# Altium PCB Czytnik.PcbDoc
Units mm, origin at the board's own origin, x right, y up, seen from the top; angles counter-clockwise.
Board outline 102 x 67 mm, 2 copper layers (Top Layer, Bottom Layer); 21 components, 15 nets, 82 pads, 16 vias.
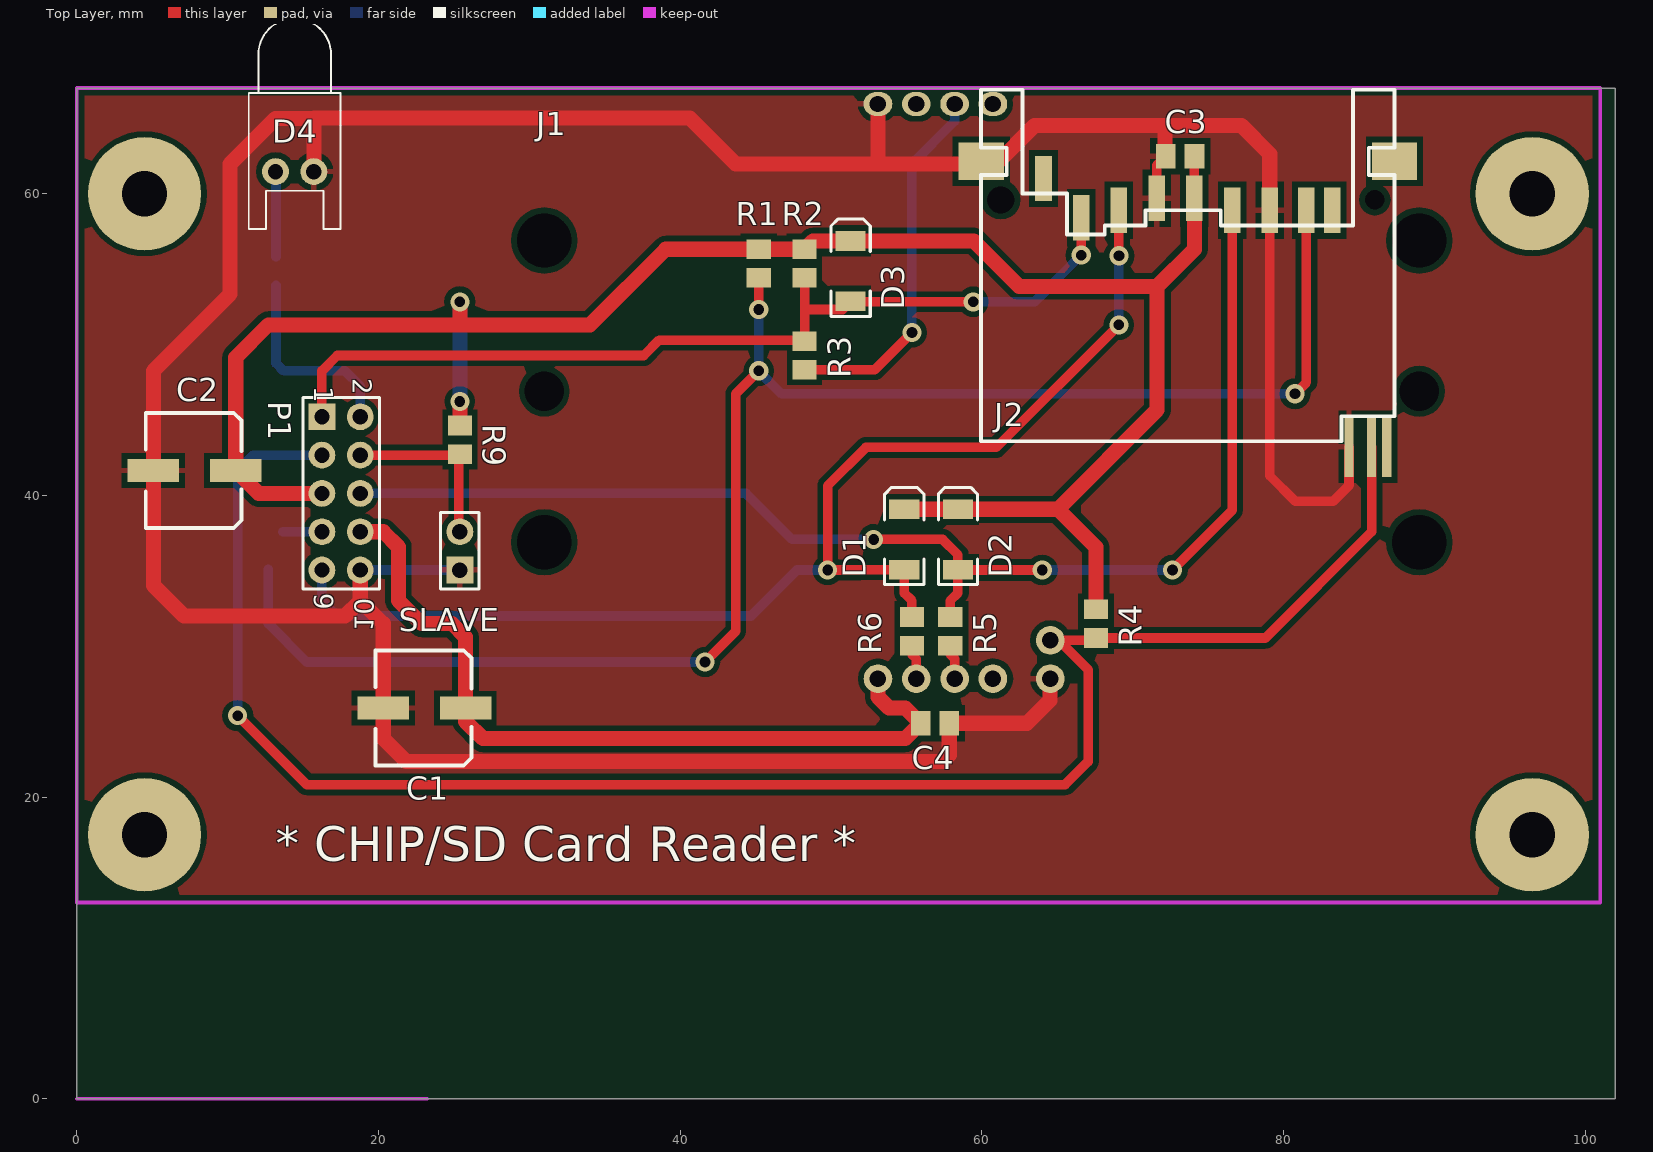
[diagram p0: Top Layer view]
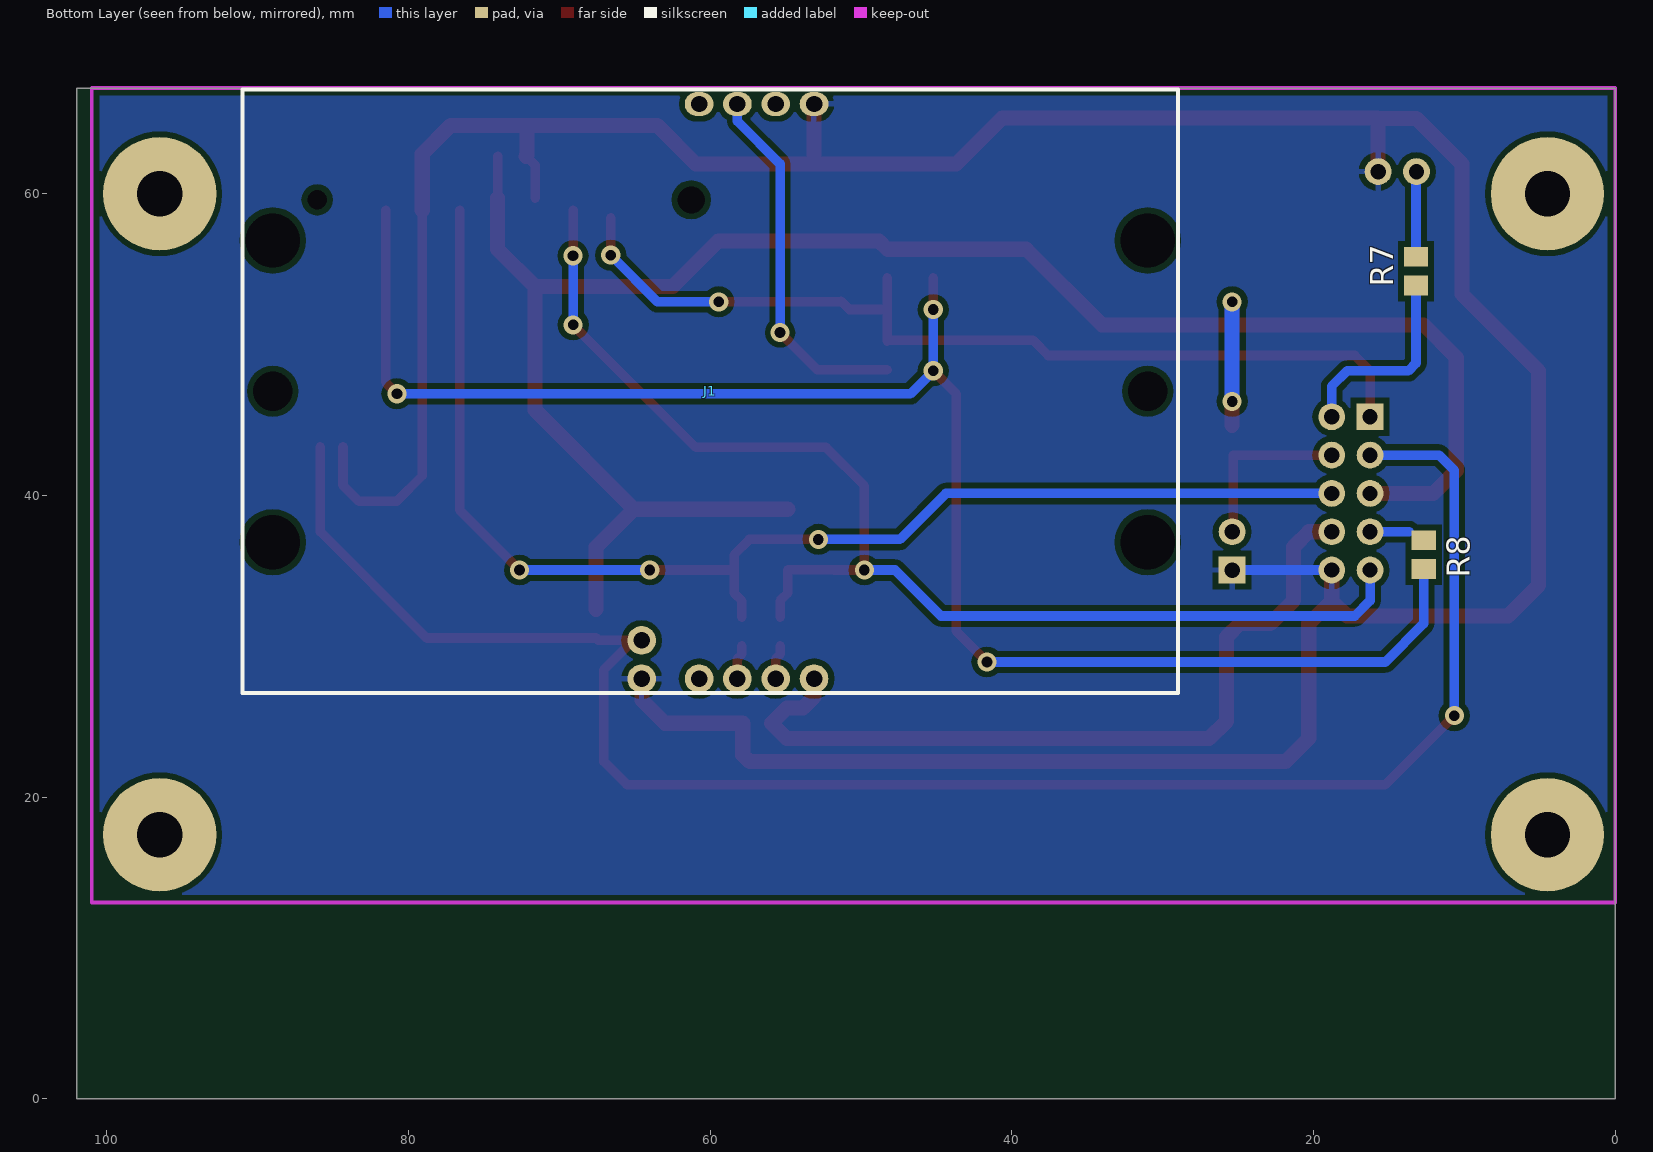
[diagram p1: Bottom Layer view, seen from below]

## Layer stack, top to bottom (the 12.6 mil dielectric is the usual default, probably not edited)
Top Layer: signal copper 0.0356
Dielectric: dielectric 0.32, FR-4, Dk 4.8
Bottom Layer: signal copper 0.0356

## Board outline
0,0 0,67 102,67 102,0 0,0

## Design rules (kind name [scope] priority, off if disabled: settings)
Clearance Clearance_10 [InNamedPolygon('Top Layer-GND')] p1: gap=0.381
Clearance Clearance_9 [InNamedPolygon('Bottom-GND')] p2: gap=0.381
Clearance Clearance_8 [InNamedPolygon('Bottom-GND')] p3: gap=0.381
Clearance Clearance_7 [InNamedPolygon('Top Layer-GND')] p4: gap=0.508
Clearance Clearance_6 [InNamedPolygon('Top Layer-GND')] p5: gap=0.254
Clearance Clearance_5 [InNamedPolygon('Top Layer-GND')] p6: gap=0.8
Clearance Clearance_4 [InNamedPolygon('Top Layer-GND')] p7: gap=0.5
Clearance Clearance_3 [InNamedPolygon('Top Layer-VCC3')] p8: gap=2
Clearance Clearance_2 [InNamedPolygon('Top Layer-VCC3')] p9: gap=1.5
Clearance Clearance_1 [InNamedPolygon('Top Layer-GND')] p10: gap=1
Clearance [All] p11: gap=0.254
PolygonConnect PolygonConnect_9 [All vs IsNamedPolygon('Bottom-GND')] p1: connectstyle=Relief reliefconductorwidth=0.381 reliefentries=4 polygonreliefangle="90 Angle"
PolygonConnect PolygonConnect_8 [All vs IsNamedPolygon('Top Layer-GND')] p2: connectstyle=Relief reliefconductorwidth=0.381 reliefentries=4 polygonreliefangle="90 Angle"
PolygonConnect PolygonConnect_7 [All vs IsNamedPolygon('Top Layer-GND')] p3: connectstyle=Relief reliefconductorwidth=0.254 reliefentries=4 polygonreliefangle="90 Angle"
PolygonConnect PolygonConnect_6 [All vs IsNamedPolygon('Top Layer-GND')] p4: connectstyle=Relief reliefconductorwidth=1.5 reliefentries=4 polygonreliefangle="90 Angle"
PolygonConnect PolygonConnect_5 [All vs IsNamedPolygon('Top Layer-GND')] p5: connectstyle=Relief reliefconductorwidth=20 reliefentries=4 polygonreliefangle="90 Angle"
PolygonConnect PolygonConnect_4 [All vs IsNamedPolygon('Top Layer-VCC3')] p6: connectstyle=Relief reliefconductorwidth=1 reliefentries=4 polygonreliefangle="90 Angle"
PolygonConnect PolygonConnect_3 [All vs IsNamedPolygon('Top Layer-VCC3')] p7: connectstyle=NoConnect reliefconductorwidth=0.254 reliefentries=4 polygonreliefangle="90 Angle"
PolygonConnect PolygonConnect_2 [All vs IsNamedPolygon('Top Layer-GND')] p8: connectstyle=NoConnect reliefconductorwidth=0.254 reliefentries=4 polygonreliefangle="90 Angle"
PolygonConnect PolygonConnect_1 [All vs IsNamedPolygon('Top Layer-GND')] p9: connectstyle=NoConnect reliefconductorwidth=0.254 reliefentries=4 polygonreliefangle="90 Angle"
PolygonConnect [All] p10: connectstyle=Relief reliefconductorwidth=0.254 reliefentries=4 polygonreliefangle="90 Angle"
RoomDefinition Sheet1 [InComponentClass('Sheet1')] p1: confinementstyle=ConfineIn formatcopy=TRUE lockcomponents=FALSE outline 0,67 102,67 102,0 0,0
RoutingVias [All] p1: holewidth=0.711 width=1.27 viastyle="Through Hole" minholewidth=0.711 minwidth=1.27 maxholewidth=0.711 maxwidth=1.27
SilkscreenOverComponentPads [All] p1: minsilkscreentomaskgap=0.254
SolderMaskExpansion [All] p1: expansion=0.102
TestPointUsage FabricationTestPointUsage [All] p1: valid=0 allowmultiple=FALSE
Testpoint FabricationTestpoint [All] p1: side=3 testpointundercomponent=TRUE minsize=1.016 maxsize=2.54 preferedsize=1.524 minholesize=0 maxholesize=1.016 preferedholesize=0.813 testpointgrid=0.025 style=297 order=0123456789
Width 40mil [InNetClass('New Class')] p1: maxlimit=1.016 minlimit=1.016 preferedwidth=1.016
23 further rules are at their usual default settings.

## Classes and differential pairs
component class Sheet1: C1 C2 C3 C4 D1 D2 D3 D4 J1 J2 P1 R1 R2 R3 R4 R5 R6 R7

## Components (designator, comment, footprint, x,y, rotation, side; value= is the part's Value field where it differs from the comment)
C1 "Cap Pol1" "ELNA 47uF SMD" 21.844,25.908 r270 top
C2 "Cap Pol1" "ELNA 47uF SMD" 6.604,41.656 r270 top
C3 "Cap" MELF-R2012-0805 73.152,62.484 r0 top
C4 "Cap" MELF-R2012-0805 56.896,24.892 r180 top
D1 "BAT43" BAT43 54.864,37.084 r90 top
D2 "BAT43" BAT43 58.42,37.084 r90 top
D3 "BAT43" BAT43 51.308,54.864 r90 top
D4 "LED0" LED-0 14.45,61.468 r180 top locked
J1 "CHIP CARD CONNECTOR" ChipCardFootprint 60,46.9 r0 bottom locked
J2 "SD Card Reader" SDCardFootprint 73.66,55.245 r180 top locked
P1 "Header 5X2" HDR2X5 16.256,45.212 r270 top
P2 "SLAVE" HDR1X2 25.4,35.052 r90 top
R1 "Res2" MELF-R2012-0805 45.212,55.372 r90 top
R2 "Res2" MELF-R2012-0805 48.26,55.372 r90 top
R3 "Res2" MELF-R2012-0805 48.26,49.276 r90 top
R4 "Res2" MELF-R2012-0805 67.564,31.496 r90 top
R5 "Res2" MELF-R2012-0805 57.912,30.988 r90 top
R6 "Res2" MELF-R2012-0805 55.372,30.988 r90 top
R7 "Res2" MELF-R2012-0805 13.208,54.864 r270 bottom
R8 "Res2" MELF-R2012-0805 12.7,36.068 r270 bottom
R9 "Res2" MELF-R2012-0805 25.4,43.688 r90 top

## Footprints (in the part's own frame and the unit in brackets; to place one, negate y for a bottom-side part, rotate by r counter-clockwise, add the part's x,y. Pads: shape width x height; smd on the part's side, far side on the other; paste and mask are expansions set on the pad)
BAT43 [mm] "DO-214-AB/SMC; 2 C-Bend Leads; Body 7.9 x 5.9 mm, inc. leads (LxW)"
  rect 1.3x2 smd: 1(-2,0) 2(2,0)
  silkscreen extent -3,-1.3 3.45,1.3
ChipCardFootprint [mm]
  round 1.9 hole 1.092: 1(-6.88,19.05) 2(-4.34,19.05) 3(-1.8,19.05) 4(0.74,19.05) 5(4.55,19.05) 6(4.55,16.51)
  oval 1.9x1.6 hole 1.092: 7(0.74,-19.05) 8(-1.8,-19.05) 9(-4.34,-19.05) 10(-6.88,-19.05)
  round 0 hole 3.6: Hole(-29,-10) Hole(-29,10) Hole(29,-10) Hole(29,10)
  round 0 hole 2.6: Hole(-29,0) Hole(29,0)
  silkscreen extent -31,-20 31,20
"ELNA 47uF SMD" [mil] "ELNA 47uF SMD"
  rect 60x133.86 smd: 1(0,155) 2(0,-60)
  silkscreen extent -150,-80 150,170
HDR1X2 [mil] "Connector; Header; 2 Position"
  rect 70x70 hole 40.5: 1(0,0)
  round 70 hole 40.5: 2(100,0)
  silkscreen extent -50,-50 150,50
HDR2X5 [mil] "Connector; Header; 5x2 Position"
  rect 70x70 hole 40: 1(0,0)
  round 70 hole 40: 2(0,100) 3(100,0) 4(100,100) 5(200,0) 6(200,100) 7(300,0) 8(300,100) 9(400,0) 10(400,100)
  silkscreen extent -50,-50 450,150
LED-0 [mil] "Typical INFRARED GaAs LED; 2 Leads"
  round 70 hole 40: 1(50,0) 2(-50,0)
  silkscreen extent -120,-400 120,150
MELF-R2012-0805 [mm] "Metal Electrode Face (MELF) Resistor; Body 2 x 1.4 mm (LxDia)"
  rect 1.3x1.6 smd: 1(-0.95,0) 2(0.95,0)
SDCardFootprint [mm]
  rect 1.1x3 smd: 1(7.065,-3.16) 2(4.565,-3.66) 3(2.065,-4.46) 4(-0.435,-4.46) 5(-2.935,-3.66) 6(-5.435,-3.66) 7(-7.865,-3.66) 8(-9.565,-3.66) 9(9.565,-5.76)
  rect 0.6x4 smd: 10(-13.19,12.025) 11(-12.19,12.025) 12(-10.69,12.025)
  round 0 hole 1.3: HOLE(-12.4,-4.35)
  round 0 hole 1.8: HOLE(12.4,-4.35)
  rect 3x2.5 smd: ML(13.7,-6.9) MR(-13.7,-6.9)
  silkscreen extent -13.7,-11.65 13.7,11.65

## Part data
C1 C2: "Polarized Capacitor (Radial)"
C3 C4: "Capacitor"
D1 D2 D3: library part Diode, "Default Diode"
D4: "Typical INFRARED GaAs LED"
J1: library part ChipCard
P1: "Header, 5-Pin, Dual row"
P2: library part "Header 2", "Header, 2-Pin"
R1 R2 R3 R4 R5 R6 R7 R8 R9: "Resistor"

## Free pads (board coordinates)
  round 7.5 hole 3: D(4.5,17.5) D(4.5,60) D(96.5,17.5) D(96.5,60)

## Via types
v1: diameter 1.27, hole 0.711, Top Layer to Bottom Layer, 16 vias

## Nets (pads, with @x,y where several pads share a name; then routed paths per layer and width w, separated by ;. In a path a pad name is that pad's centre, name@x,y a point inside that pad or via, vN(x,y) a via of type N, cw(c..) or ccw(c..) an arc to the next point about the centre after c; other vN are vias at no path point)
CHIP/SD_CD: J1.6 J2.11 P1.3 R4.1 | length 119.9
  Top Layer w0.635: v1(10.668,25.4) 15.24,20.828 65.532,20.828 67.056,22.352 67.056,28.448 J1.6@65.114,30.39 ; J1.6 J1.6@65.114,30.39 ; J2.11 85.85,37.59 78.806,30.546 R4.1 67.408,30.39 J1.6@65.114,30.39
  Bottom Layer w0.635: v1(10.668,25.4) 10.668,41.656 11.684,42.672 P1.3
CHIP/SD_CLK: D2.1 J2.5 P1.6 R5.2 | length 85.4
  Top Layer w0.635: v1(52.832,37.084) 57.404,37.084 58.42,36.068 D2.1 ; R5.2 57.912,33.02 58.42,33.528 D2.1 ; v1(64.008,35.052) 58.452,35.052 D2.1 ; v1(72.644,35.052) 76.595,39.003 J2.5
  Bottom Layer w0.635: P1.6 44.377,40.132 47.425,37.084 v1(52.832,37.084) ; v1(64.008,35.052) v1(72.644,35.052)
GND: C1.2 C2.2 C3.1 C4.1 D4.2 J1.5 J1.10 J2.3 J2.6 J2.12 P1.10 P2.1 | length 228.9
  Top Layer w0.635: J2.3 71.595,61.877 C3.1 ; J2.6 79.095,41.301 80.772,39.624 83.312,39.624 84.35,40.662 J2.12
  Top Layer w1: D4.2 15.72,64.996 ; P1.10 18.796,33.02 ; J1.10 53.12,62.196 53.34,61.976 ; C4.1@57.912,24.892 C4.1 ; J1.5 64.516,27.816 64.516,26.416 62.992,24.892 C4.1 ; C3.1 72.136,62.55 72.136,64.516 ; J2.6 79.095,62.637 77.216,64.516 72.136,64.516 ; 15.72,64.996 13.18,64.996 10.16,61.976 10.16,53.34 5.08,48.26 C2.2 5.08,34.036 7.112,32.004 17.78,32.004 18.796,33.02 ; 15.72,64.996 15.748,65.024 40.64,65.024 43.688,61.976 53.34,61.976 ; 18.796,33.02 20.32,31.496 C1.2 20.32,23.876 21.844,22.352 57.404,22.352 57.846,22.794 C4.1 ; 53.34,61.976 60.96,61.976 63.5,64.516 72.136,64.516
  Bottom Layer w0.635: P1.10 P2.1
LED_G: P1.2 R7.2 | length 13.4
  Bottom Layer w0.635: R7.2 13.208,48.768 13.716,48.26 17.78,48.26 18.796,47.244 P1.2
NetD4_1: D4.1 R7.1 | length 5.7
  Top Layer w0.635: D4.1 D4.1@13.208,61.44
  Bottom Layer w0.635: D4.1 13.208,61.44 R7.1
NetJ1_2: J1.2 R6.1 | length 2.3
  Top Layer w0.635: R6.1 55.372,29.464 55.66,29.176 J1.2
NetJ1_3: J1.3 R5.1 | length 2.3
  Top Layer w0.635: R5.1 57.912,29.464 58.2,29.176 J1.3
NetJ1_8: J1.8 R3.1 | length 25.1
  Top Layer w0.635: R3.1 51.308,48.326 52.898,48.326 v1(55.372,50.8)
  Bottom Layer w0.635: v1(55.372,50.8) 55.372,61.976 58.2,64.804 J1.8 J1.8@58.2,65.312
NetP1_7: P1.7 R8.1 | length 2.6
  Bottom Layer w0.635: 13.65,37.592 P1.7
SD_CS/CHIP_IO: D3.1 J2.1 P1.1 R2.1 R3.2 | length 62.4
  Top Layer w0.635: P1.1 16.256,48.26 17.272,49.276 37.592,49.276 38.608,50.292 R3.2@48.26,50.292 ; R3.2 R3.2@48.26,50.292 ; R2.1 48.26,52.324 ; v1(59.436,52.832) 51.34,52.832 D3.1 50.768,52.324 48.26,52.324 ; v1(66.595,55.927) J2.1 ; R3.2@48.26,50.292 48.26,52.324
  Bottom Layer w0.635: v1(59.436,52.832) 63.5,52.832 v1(66.595,55.927)
SD_DI/CHIP_RST: D1.1 J2.2 P1.9 R6.2 | length 82.6
  Top Layer w0.635: R6.2 55.372,33.02 54.864,33.528 D1.1 51.848,35.084 51.816,35.052 v1(49.784,35.052) 49.784,40.64 52.324,43.18 60.96,43.18 v1(69.088,51.308) ; v1(69.095,55.887) J2.2
  Bottom Layer w0.635: P1.9 16.256,33.02 17.272,32.004 44.704,32.004 47.752,35.052 v1(49.784,35.052) ; v1(69.088,51.308) 69.095,51.315 v1(69.095,55.887) v1@69.088,55.88
SD_DO: J2.7 R1.1 R8.2 | length 110.3
  Top Layer w0.635: v1(41.656,28.956) 43.688,30.988 43.688,46.736 v1(45.212,48.26) ; v1(45.212,52.324) R1.1 ; v1(80.772,46.736) 81.525,47.489 J2.7
  Bottom Layer w0.635: 12.7,32.004 12.7,33.02 ; R8.2 12.7,33.02 ; v1(41.656,28.956) 15.24,28.956 12.7,31.496 12.7,33.02 ; v1(45.212,52.324) v1(45.212,48.26) 46.736,46.736 v1(80.772,46.736)
SW: P1.4 P2.2 R9.1 | length 11.6
  Top Layer w0.635: P1.4 25.334,42.672 P2.2@25.334,37.658
VCC: C1.1 C4.2 J1.1 P1.8 | length 53.4
  Top Layer w1: P1.8 20.32,37.592 21.336,36.576 21.336,33.02 22.86,31.496 24.892,31.496 25.781,30.607 C1.1 25.781,25.019 26.924,23.876 54.93,23.876 C4.2 54.93,25.908 53.848,25.908 53.12,26.636 J1.1
VCC3: C2.1 C3.2 D1.2 D2.2 D3.2 J2.4 P1.5 R1.2 R2.2 R4.2 R9.2 | length 134.1
  Top Layer w0.635: J2.4 74.102,59.712 C3.2
  Top Layer w1: P1.5 12.065,40.132 C2.1 10.541,49.149 12.7,51.308 25.4,51.308 ; R9.2 v1(25.4,46.228) ; v1(25.4,52.832) 25.4,51.308 ; D1.2 D2.2 65.056,39.084 ; R4.2 67.564,36.576 65.056,39.084 ; J2.4 74.095,56.315 71.628,53.848 ; 25.4,51.308 34.036,51.308 39.05,56.322 R1.2 R2.2 48.802,56.864 D3.2 59.468,56.864 62.484,53.848 71.628,53.848 ; 65.056,39.084 71.628,45.656 71.628,53.848
  Bottom Layer w1: v1(25.4,46.228) v1(25.4,52.832)
pads on no net: J1.4 J1.7 J1.9 J1.Hole J2.8 J2.9 J2.10 J2.HOLE J2.ML J2.MR

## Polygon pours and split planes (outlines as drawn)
GND on Top Layer "Top Layer-GND" (solid, remove dead copper, pour order 1001): 0.113,-0.073 0.113,66.927 102.113,66.927 102.113,-0.073 0.113,-0.073
GND on Bottom Layer "Bottom-GND" (solid, remove dead copper, pour order 1000): 0.508,66.548 101.6,66.548 101.6,13 0.508,13

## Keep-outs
Top Layer:
  lines w0.254: 0,0 23.241,0
Keep-Out Layer:
  lines w0.254: 0,13 0,67 101,67 101,13 0,13

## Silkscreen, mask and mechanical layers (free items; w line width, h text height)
Top Overlay:
  text "* CHIP/SD Card Reader *" at 13.208,15.748 h2.29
